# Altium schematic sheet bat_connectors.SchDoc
size A3; DocumentNumber: 14; SheetNumber: 14; SheetTotal: 15; SheetDescription: Connection to pack
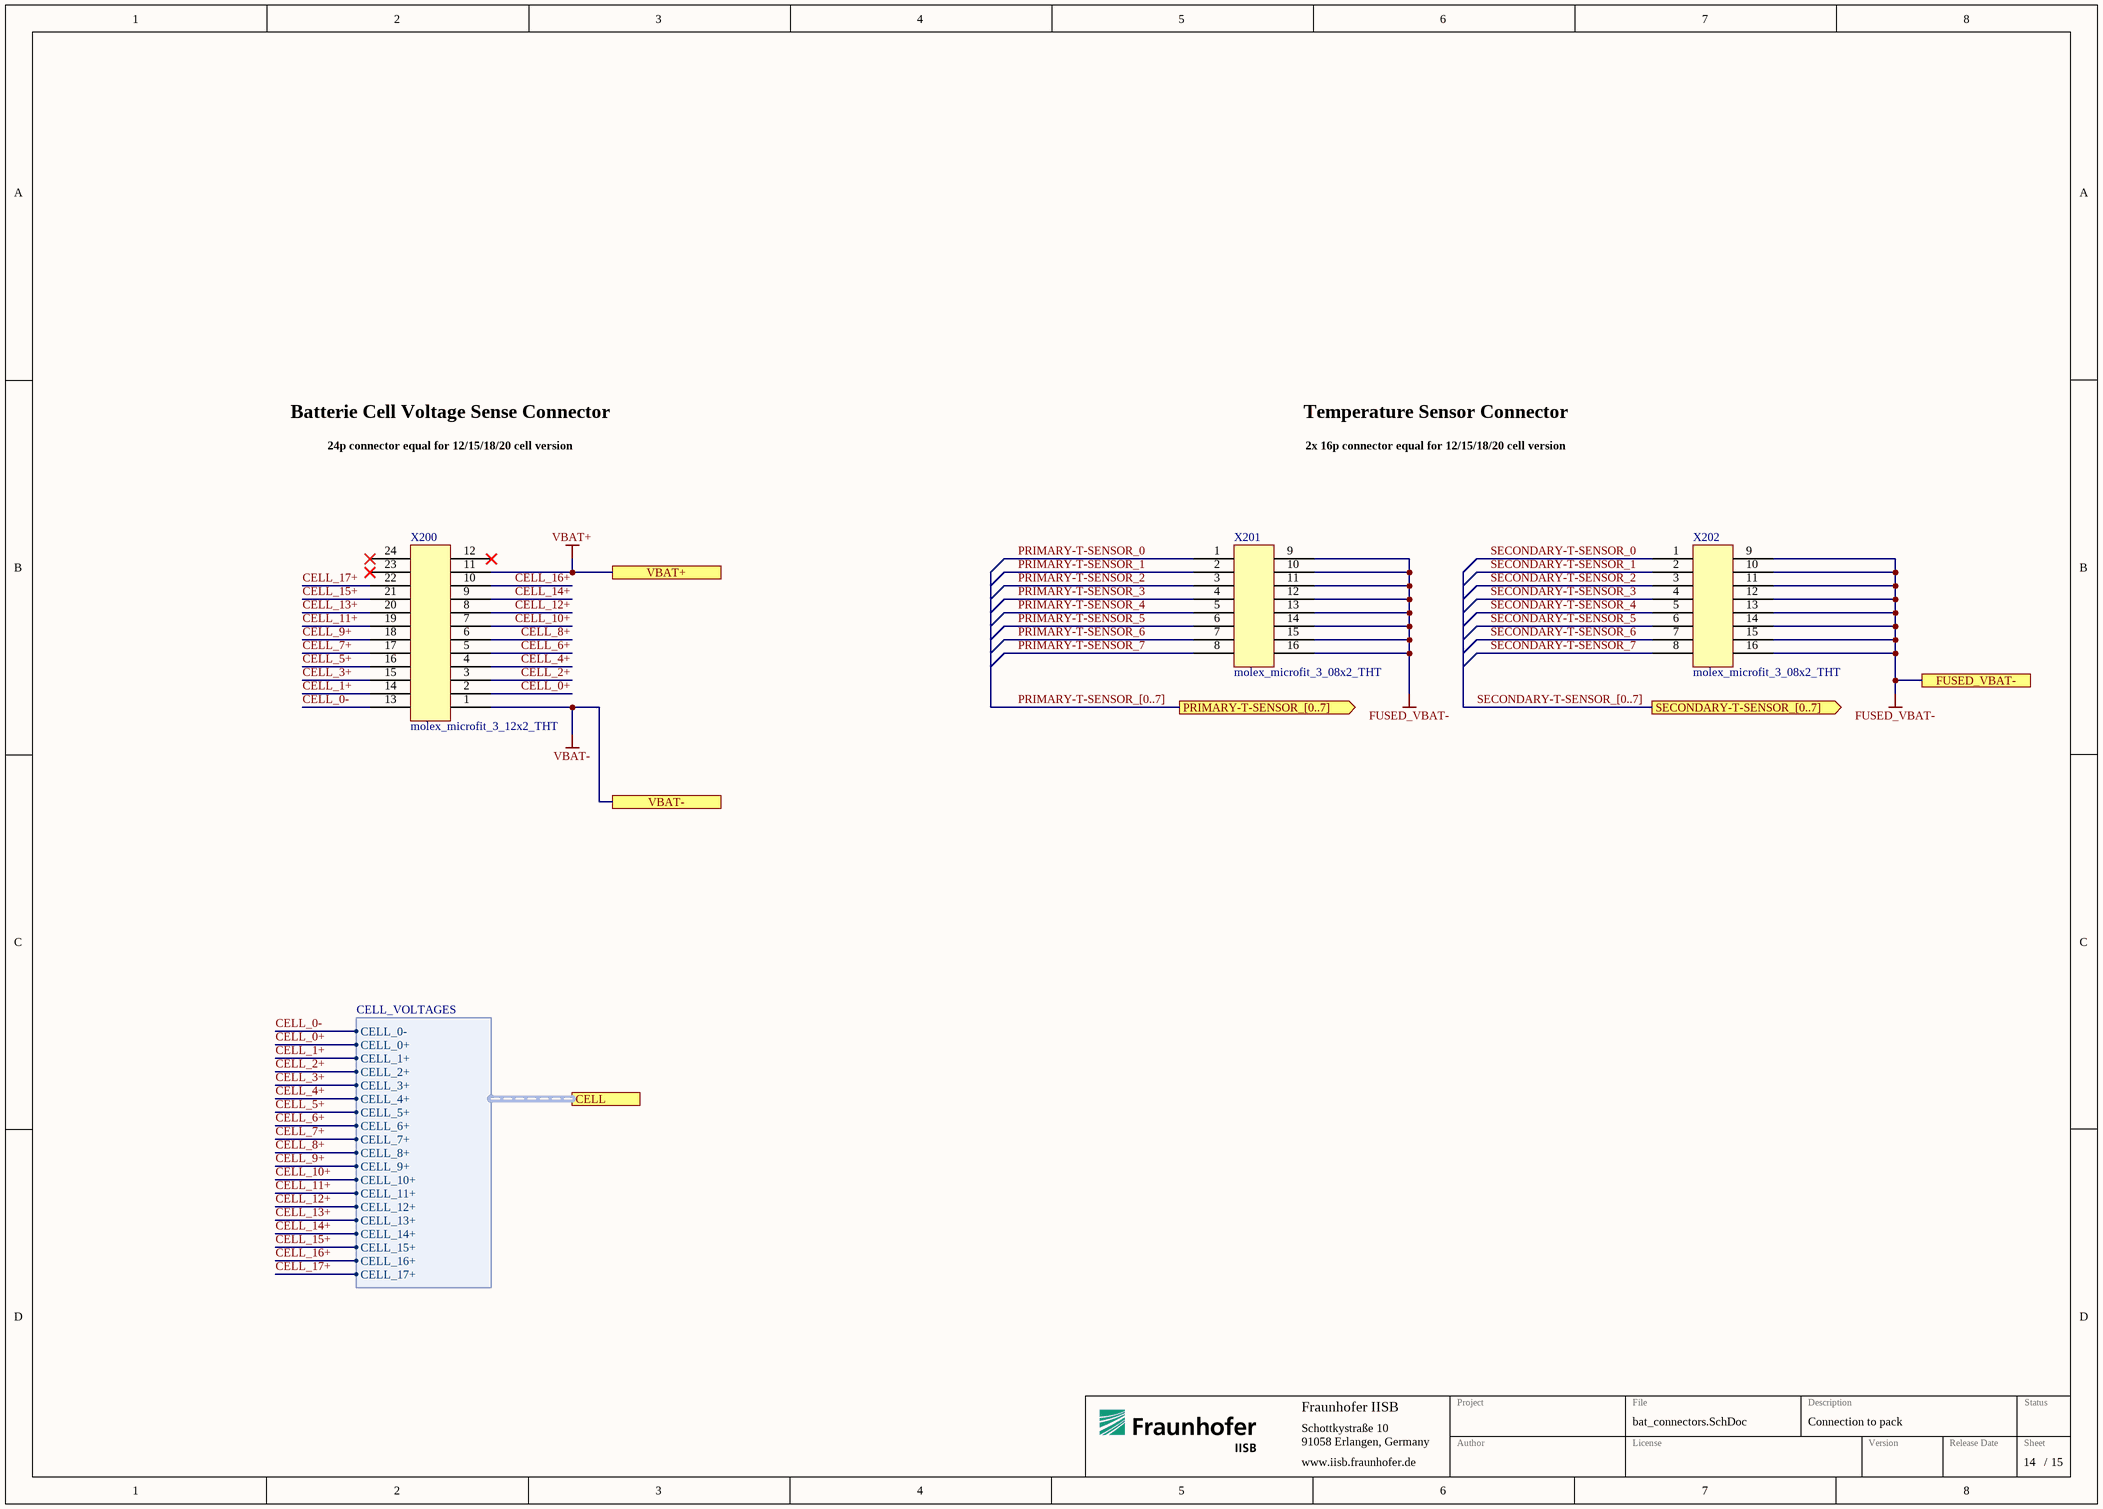
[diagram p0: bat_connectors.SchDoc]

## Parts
X200  molex_microfit_3_12x2_THT  [MOLEX_MICROFIT_12x2_THT]
X201  molex_microfit_3_08x2_THT  [MOLEX_MICROFIT_08x2_THT]
X202  molex_microfit_3_08x2_THT  [MOLEX_MICROFIT_08x2_THT]

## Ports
CELL (harness CELL_VOLTAGES), FUSED_VBAT-, PRIMARY-T-SENSOR_[0..7] (out), SECONDARY-T-SENSOR_[0..7] (out), VBAT+, VBAT-

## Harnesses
CELL_VOLTAGES: CELL_0-, CELL_0+, CELL_1+, CELL_2+, CELL_3+, CELL_4+, CELL_5+, CELL_6+, CELL_7+, CELL_8+, CELL_9+, CELL_10+, CELL_11+, CELL_12+, CELL_13+, CELL_14+, CELL_15+, CELL_16+, CELL_17+

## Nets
FUSED_VBAT-: X201.9 X201.10 X201.11 X201.12 X201.13 X201.14 X201.15 X201.16 X202.9 X202.10 X202.11 X202.12 X202.13 X202.14 X202.15 X202.16 ; port FUSED_VBAT-
VBAT+: X200.11 ; port VBAT+
VBAT-: X200.1 ; port VBAT-
CELL_0+: X200.2 ; port CELL.CELL_0+
CELL_0-: X200.13 ; port CELL.CELL_0-
CELL_1+: X200.14 ; port CELL.CELL_1+
CELL_2+: X200.3 ; port CELL.CELL_2+
CELL_3+: X200.15 ; port CELL.CELL_3+
CELL_4+: X200.4 ; port CELL.CELL_4+
CELL_5+: X200.16 ; port CELL.CELL_5+
CELL_6+: X200.5 ; port CELL.CELL_6+
CELL_7+: X200.17 ; port CELL.CELL_7+
CELL_8+: X200.6 ; port CELL.CELL_8+
CELL_9+: X200.18 ; port CELL.CELL_9+
CELL_10+: X200.7 ; port CELL.CELL_10+
CELL_11+: X200.19 ; port CELL.CELL_11+
CELL_12+: X200.8 ; port CELL.CELL_12+
CELL_13+: X200.20 ; port CELL.CELL_13+
CELL_14+: X200.9 ; port CELL.CELL_14+
CELL_15+: X200.21 ; port CELL.CELL_15+
CELL_16+: X200.10 ; port CELL.CELL_16+
CELL_17+: X200.22 ; port CELL.CELL_17+
PRIMARY-T-SENSOR_0: X201.1
PRIMARY-T-SENSOR_1: X201.2
PRIMARY-T-SENSOR_2: X201.3
PRIMARY-T-SENSOR_3: X201.4
PRIMARY-T-SENSOR_4: X201.5
PRIMARY-T-SENSOR_5: X201.6
PRIMARY-T-SENSOR_6: X201.7
PRIMARY-T-SENSOR_7: X201.8
SECONDARY-T-SENSOR_0: X202.1
SECONDARY-T-SENSOR_1: X202.2
SECONDARY-T-SENSOR_2: X202.3
SECONDARY-T-SENSOR_3: X202.4
SECONDARY-T-SENSOR_4: X202.5
SECONDARY-T-SENSOR_5: X202.6
SECONDARY-T-SENSOR_6: X202.7
SECONDARY-T-SENSOR_7: X202.8

Not connected (* = marked no-connect by the designer): X200 12* 23* 24*

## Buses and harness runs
bus PRIMARY-T-SENSOR_[0..7] = port PRIMARY-T-SENSOR_[0..7]
bus SECONDARY-T-SENSOR_[0..7] = port SECONDARY-T-SENSOR_[0..7]

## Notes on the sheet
- Batterie Cell Voltage Sense Connector
- 24p connector equal for 12/15/18/20 cell version
- Temperature Sensor Connector
- 2x 16p connector equal for 12/15/18/20 cell version

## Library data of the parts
X200 = molex_microfit_3_12x2_THT: Micro-Fit 3.0 Right Angle Header, 3.00mm Pitch, Dual Row, 24 Circuits, with Snap-in Plastic Peg PCB Lock, Tin, Glow Wire Capable, Black, 43045-2400; Manufacturer: Molex; Circuits: 24; Rated Voltage: 600V; Rated Current: 8.5A; Automotive Qualified: False
X201 X202 = molex_microfit_3_08x2_THT: Micro-Fit 3.0 Right Angle Header, 3.00mm Pitch, Dual Row, 16 Circuits, with Snap-in Plastic Peg PCB Lock, Tin, Glow Wire Capable, Black, 43045-1600; Manufacturer: Molex; Circuits: 16; Rated Voltage: 600V; Rated Current: 8.5A; Automotive Qualified: False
